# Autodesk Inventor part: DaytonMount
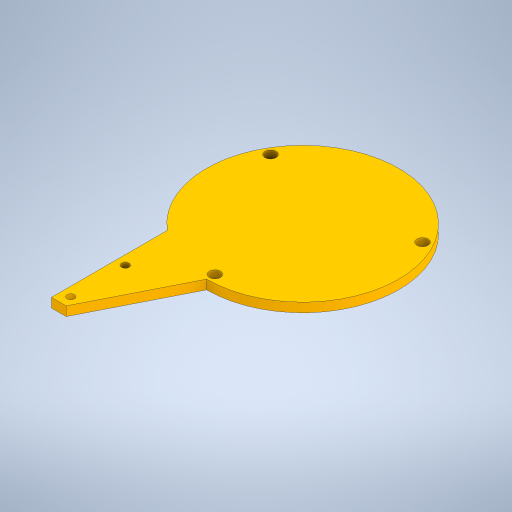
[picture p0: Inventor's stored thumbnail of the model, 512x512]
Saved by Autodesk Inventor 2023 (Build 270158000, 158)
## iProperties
Created: 2023-06
Part Number: DaytonMount
Material: Generic
Document SubType Name: Modeling
Designer: Admin
Density: 1 g/cm^3
Appearance: Default
Author: Admin
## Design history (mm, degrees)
sketch "Sketch1" dims "d18" = 4, "d43" = 95
  geometry: L1 (25.5, -43)-(25.5, -58); L2 (17, -25.5)-(17, -30.5); L3 (17, -30.5)-(6, -30.5); L4 (6, -30.5)-(6, -25.5); L5 (6, -25.5)-(17, -25.5); L6 (0, -153)-(0, 0); L7 (0, -153)-(0, 0); L8 (51, 0)-(51, -153); L9 (60.249, 0)-(60.249, -153); L10 (25.5, -28)-(25.5, 0); L11 (0, 0)-(51, 0); L12 (0, 0)-(60.249, 0); L13 (51, -153)-(0, -153); L14 (60.249, -153)-(0, -153); L15 (46, -60.5)-(35, -60.5); L16 (35, -60.5)-(35, -55.5); L17 (46, -55.5)-(46, -60.5); L18 (51, -33)-(59, -33); L19 (51, -75)-(51, -33); L20 (59, -33)-(59, -75); L21 (59, -75)-(51, -75); L22 (25.5, -58)-(25.5, -73); L23 (25.5, -73)-(25.5, -88); L24 (17, -60.5)-(6, -60.5); L25 (17, -55.5)-(17, -60.5); L26 (6, -55.5)-(17, -55.5); L27 (6, -60.5)-(6, -55.5); L28 (17, -90.5)-(6, -90.5); L29 (17, -85.5)-(17, -90.5); L30 (6, -85.5)-(17, -85.5); L31 (35, -85.5)-(46, -85.5); L32 (46, -90.5)-(35, -90.5); L33 (46, -85.5)-(46, -90.5); L34 (35, -90.5)-(35, -85.5); L35 (6, -90.5)-(6, -85.5); L36 (25.5, -28)-(25.5, -43); L37 (35, -30.5)-(35, -25.5); L38 (46, -25.5)-(46, -30.5); L39 (35, -25.5)-(46, -25.5); L40 (46, -30.5)-(35, -30.5); L41 (54, -40.5)-(25.5, -40.5); L42 (35, -55.5)-(46, -55.5); L43 (59, -95.729)-(59, -33); L44 (51, -33)-(59, -33); L45 (25.5, -83.5)-(51, -33); C1 r 2.5 at (25.5, -28); C2 r 2 at (54, -68); C3 r 2.5 at (25.5, -58); C4 r 2.5 at (25.5, -73); C5 r 2.5 at (25.5, -88); C6 r 3 at (25.5, -88); C7 r 3 at (66.636, -159.25); C8 r 3 at (-15.636, -159.25); C9 r 3 at (-15.636, -159.25); C10 r 3 at (66.636, -159.25); C11 r 3 at (25.5, -88); C12 r 2 at (54, -38.5); C13 r 2 at (54, -68); A1 r 52 centre (25.5, -135.5) between (25.5, -83.5) and (59, -95.729); 5 further points
  constraints: 82 end point, 14 centre point, 10 vertical alignment, 9 coincident, 8 collinear, 7 parallel, 5 concentric, 5 horizontal, 4 perpendicular, 4 point on line, 3 equal radius, 2 point on circle, 2 vertical, 1 midpoint, 1 tangent, 65 other
  dimensions: "d4" = 5 distance between parallel lines of L3 L5; "d5" = 11 distance between parallel lines of L4 L2; "d6" = 153 distance between parallel lines of L14 L11; "d7" = 51 distance between parallel lines of L6 L8; "d8" = 15 distance of L10.start L1.start; "d9" = 28 distance of L10.start L10.end; "d10" = 8 distance between parallel lines of L20 L8; "d11" = 5 diameter of C1; "d12" = 33 distance between parallel lines of L11 L18; "d13" = 42 distance of L18.end L20.end; "d14" = 6 distance between parallel lines of L6 L4; "d15" = 30 distance of L2.end L24.start; "d16" = 29 distance of L2.end L38.end; "d17" = 3 distance from line of L8 point (54, -38.5); "d19" = 29.5 distance of C2.centre point (54, -38.5); "d44" = 6 diameter of C6; "d47" = 360 deg dimension on point (25.5, -135.5) C6.centre (derived); "d61" = 52 radius of A1
extrude "Extrusion1" new body sketch "Sketch1" distance "d63" = 5; taper "d64" = 0 deg
body "Solid1"
other parameters: "d42" = 104
